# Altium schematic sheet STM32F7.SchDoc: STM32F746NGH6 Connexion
size A3; Date: 25-FEB-2015; Author: A.B; CompanyName: STMicroelectronics; Address1: 12, Rue Jules HOROWITZ; Address2: 38019 Grenoble; Address3: FRANCE; DocumentNumber: MB1191; Revision: B-02; SheetNumber: 9; SheetTotal: 13; Project: STM32F746G-DISCO
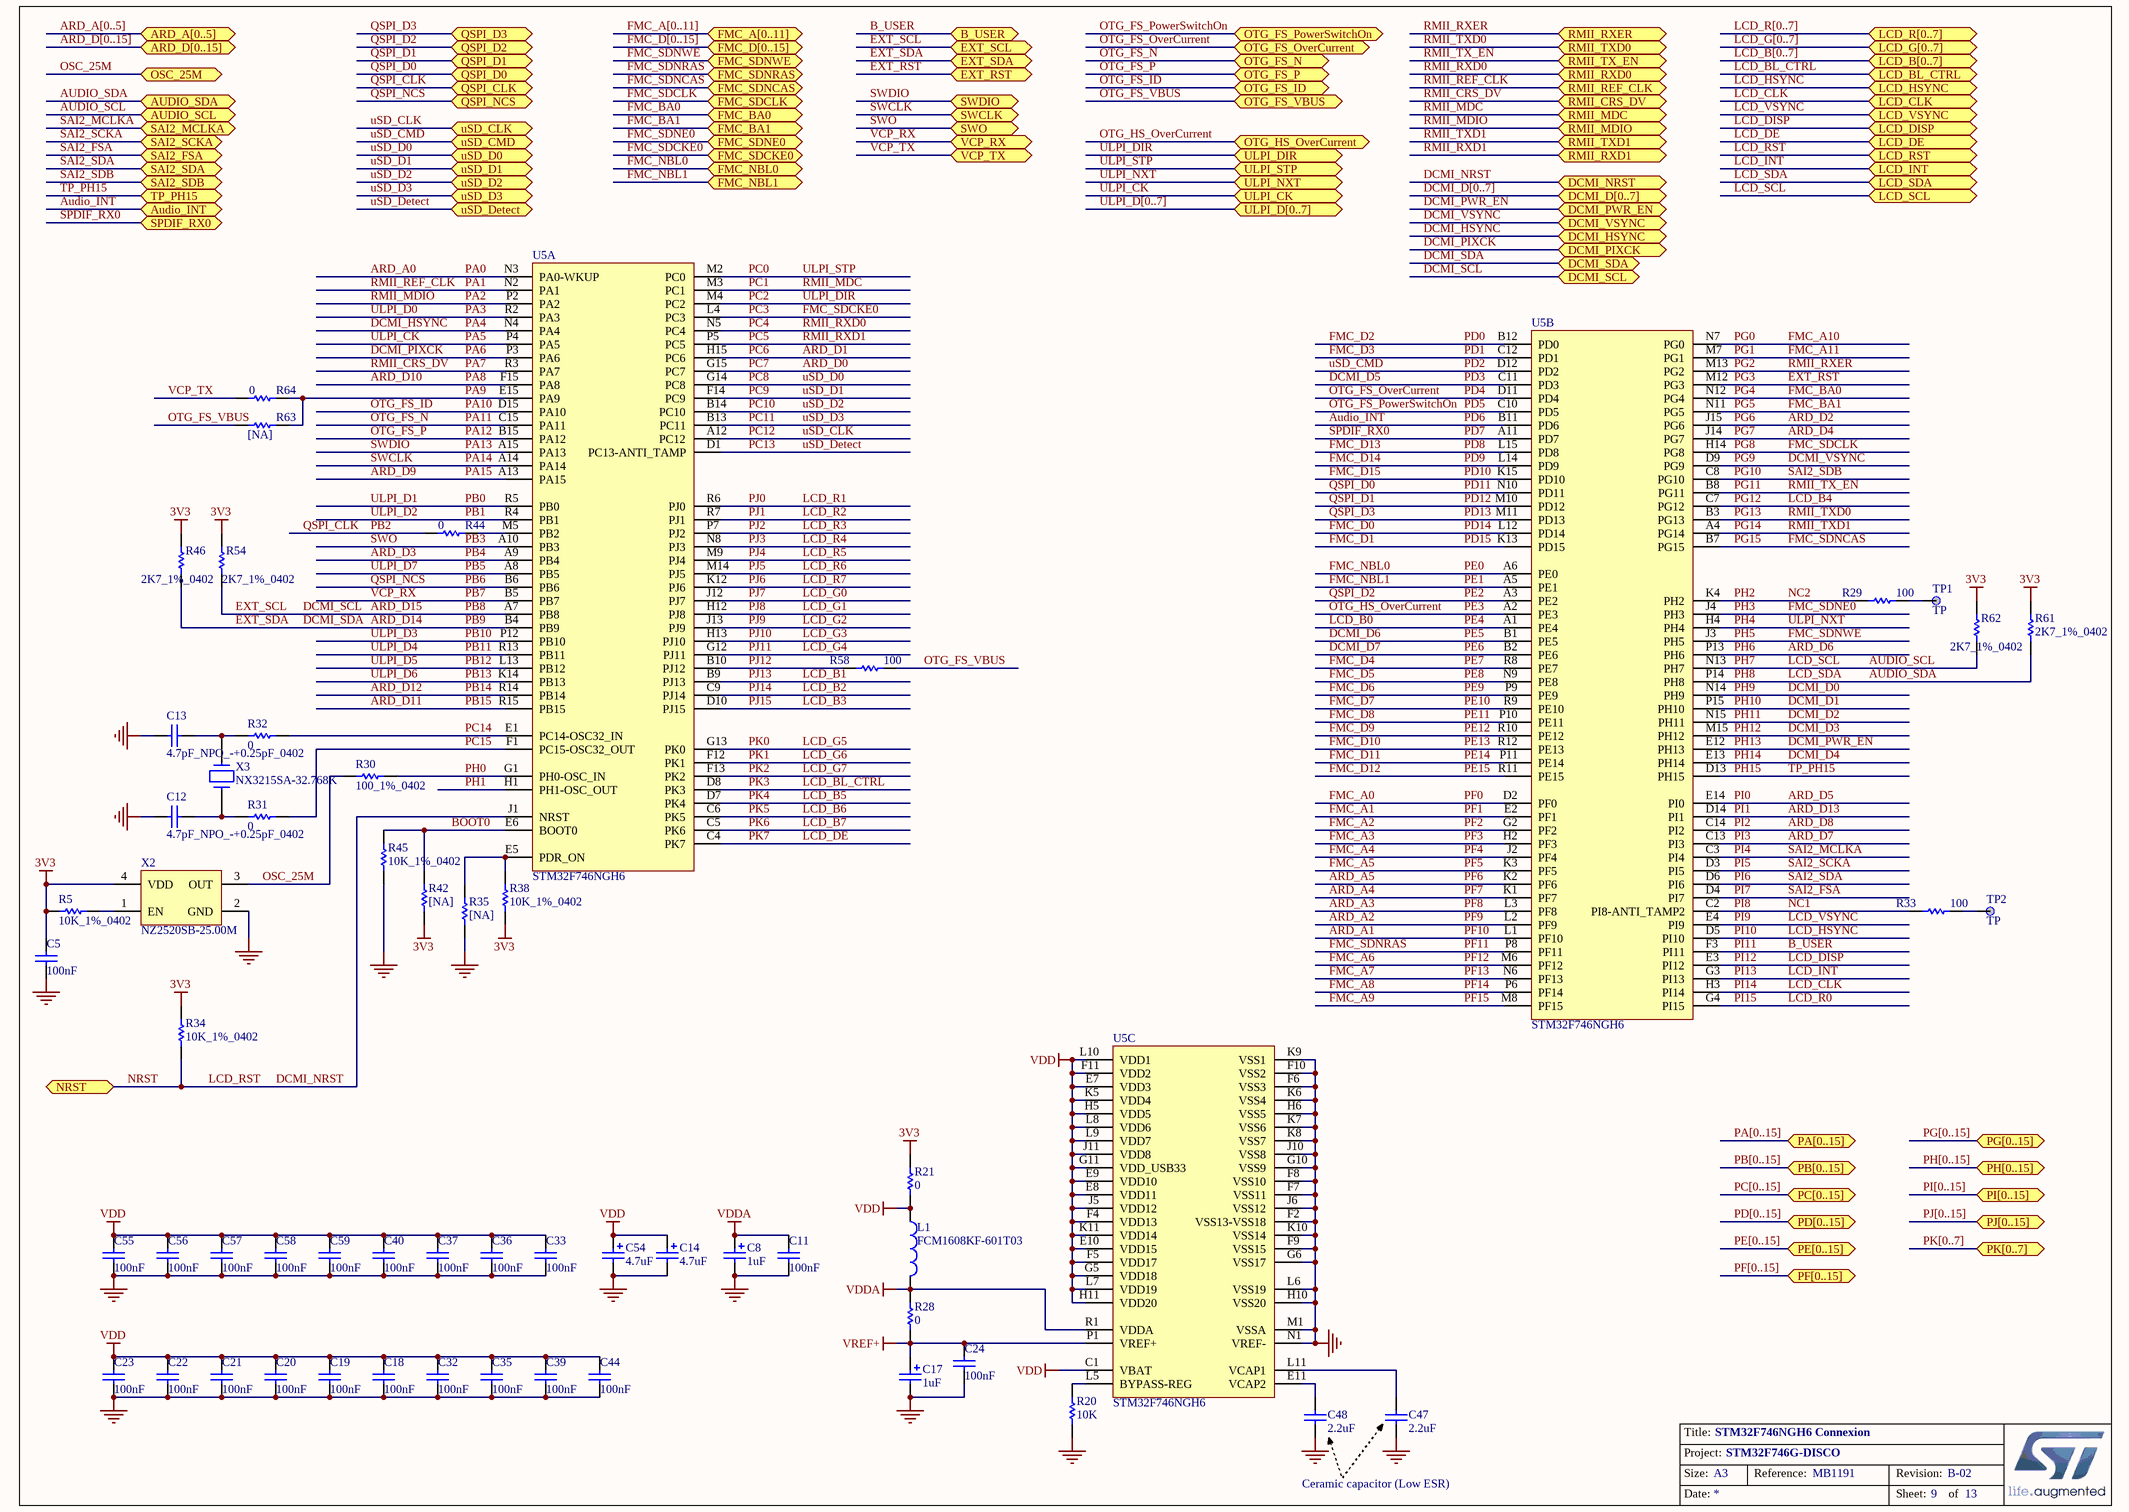
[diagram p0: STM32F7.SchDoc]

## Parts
C5  100nF  [0402C]
C8  1uF  [TAN-A]
C11  100nF  [0402C]
C12  4.7pF_NPO_-+0.25pF_0402  [0402C]
C13  4.7pF_NPO_-+0.25pF_0402  [0402C]
C14  4.7uF  [TAN-A]
C17  1uF  [TAN-A]
C18  100nF  [0402C]
C19  100nF  [0402C]
C20  100nF  [0402C]
C21  100nF  [0402C]
C22  100nF  [0402C]
C23  100nF  [0402C]
C24  100nF  [0402C]
C32  100nF  [0402C]
C33  100nF  [0402C]
C35  100nF  [0402C]
C36  100nF  [0402C]
C37  100nF  [0402C]
C39  100nF  [0402C]
C40  100nF  [0402C]
C44  100nF  [0402C]
C47  2.2uF  [1206C]
C48  2.2uF  [1206C]
C54  4.7uF  [TAN-A]
C55  100nF  [0402C]
C56  100nF  [0402C]
C57  100nF  [0402C]
C58  100nF  [0402C]
C59  100nF  [0402C]
L1  FCM1608KF-601T03  [0603L]
R5  10K_1%_0402  [0402R]
R20  10K  [0402R]
R21  0  [0603R-GS]
R28  0  [0603R-GS]
R29  100  [0402R]
R30  100_1%_0402  [0402R]
R31  0  [0402R]
R32  0  [0402R]
R33  100  [0402R]
R34  10K_1%_0402  [0402R]
R35  [NA]  [0402R]
R38  10K_1%_0402  [0402R]
R42  [NA]  [0402R]
R44  0  [0402R]
R45  10K_1%_0402  [0402R]
R46  2K7_1%_0402  [0402R]
R54  2K7_1%_0402  [0402R]
R58  100  [0402R]
R61  2K7_1%_0402  [0402R]
R62  2K7_1%_0402  [0402R]
R63  [NA]  [0402R]
R64  0  [0402R]
TP1  TP  [SMDTEST-1MM]
TP2  TP  [SMDTEST-1MM]
U5  STM32F746NGH6  [BGA216_0R8_13X13_SKT]  (parts A,B,C of 3)
X2  NZ2520SB-25.00M  [OSC_4SM_2R5X2R0]
X3  NX3215SA-32.768K  [XTAL_2SM_3R2X1R5]

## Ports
ARD_A[0..5], ARD_D[0..15], Audio_INT, AUDIO_SCL, AUDIO_SDA, B_USER, DCMI_D[0..7], DCMI_HSYNC, DCMI_NRST, DCMI_PIXCK, DCMI_PWR_EN, DCMI_SCL, DCMI_SDA, DCMI_VSYNC, EXT_RST, EXT_SCL, EXT_SDA, FMC_A[0..11], FMC_BA0, FMC_BA1, FMC_D[0..15], FMC_NBL0, FMC_NBL1, FMC_SDCKE0, FMC_SDCLK, FMC_SDNCAS, FMC_SDNE0, FMC_SDNRAS, FMC_SDNWE, LCD_B[0..7], LCD_BL_CTRL, LCD_CLK, LCD_DE, LCD_DISP, LCD_G[0..7], LCD_HSYNC, LCD_INT, LCD_R[0..7], LCD_RST, LCD_SCL, LCD_SDA, LCD_VSYNC, NRST, OSC_25M, OTG_FS_ID, OTG_FS_N, OTG_FS_OverCurrent, OTG_FS_P, OTG_FS_PowerSwitchOn, OTG_FS_VBUS, OTG_HS_OverCurrent, PA[0..15], PB[0..15], PC[0..15], PD[0..15], PE[0..15], PF[0..15], PG[0..15], PH[0..15], PI[0..15], PJ[0..15], PK[0..7], QSPI_CLK, QSPI_D0, QSPI_D1, QSPI_D2, QSPI_D3, QSPI_NCS, RMII_CRS_DV, RMII_MDC, RMII_MDIO, RMII_REF_CLK, RMII_RXD0, RMII_RXD1, RMII_RXER, RMII_TX_EN, RMII_TXD0, RMII_TXD1, SAI2_FSA, SAI2_MCLKA, SAI2_SCKA, SAI2_SDA, SAI2_SDB, SPDIF_RX0, SWCLK, SWDIO, SWO, TP_PH15, ULPI_CK, ULPI_D[0..7], ULPI_DIR, ULPI_NXT, ULPI_STP, uSD_CLK, uSD_CMD, uSD_D0, uSD_D1, uSD_D2, uSD_D3, uSD_Detect, VCP_RX, VCP_TX

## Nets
3V3: C5.2 R5.1 R21.2 R34.2 R38.1 R42.1 R46.2 R54.2 R61.2 R62.2 X2.4(VDD)
GND: C5.1 C8.2 C11.1 C12.1 C13.1 C14.2 C17.2 C18.1 C19.1 C20.1 C21.1 C22.1 C23.1 C24.1 C32.1 C33.1 C35.1 C36.1 C37.1 C39.1 C40.1 C44.1 C47.1 C48.1 C54.2 C55.1 C56.1 C57.1 C58.1 C59.1 R20.1 R35.1 R45.1 U5.F2(VSS13-VSS18) U5.F6(VSS3) U5.F7(VSS11) U5.F8(VSS10) U5.F9(VSS15) U5.F10(VSS2) U5.G6(VSS17) U5.G10(VSS9) U5.H6(VSS5) U5.H10(VSS20) U5.J6(VSS12) U5.J10(VSS8) U5.K6(VSS4) U5.K7(VSS6) U5.K8(VSS7) U5.K9(VSS1) U5.K10(VSS14) U5.L6(VSS19) U5.M1(VSSA) U5.N1(VREF-) X2.2(GND)
VDD: C14.1 C18.2 C19.2 C20.2 C21.2 C22.2 C23.2 C32.2 C33.2 C35.2 C36.2 C37.2 C39.2 C40.2 C44.2 C54.1 C55.2 C56.2 C57.2 C58.2 C59.2 L1.1 R21.1 U5.C1(VBAT) U5.E7(VDD3) U5.E8(VDD11) U5.E9(VDD10) U5.E10(VDD15) U5.F4(VDD13) U5.F5(VDD17) U5.F11(VDD2) U5.G5(VDD18) U5.G11(VDD_USB33) U5.H5(VDD5) U5.H11(VDD20) U5.J5(VDD12) U5.J11(VDD8) U5.K5(VDD4) U5.K11(VDD14) U5.L7(VDD19) U5.L8(VDD6) U5.L9(VDD7) U5.L10(VDD1)
VDDA: C8.1 C11.2 L1.2 R28.1 U5.R1(VDDA)
VREF+: C17.1 C24.2 R28.2 U5.P1(VREF+)
ARD_A0: U5.N3(PA0-WKUP)  [also labelled PA0]
ARD_A1: U5.L1(PF10)  [also labelled PF10]
ARD_A2: U5.L2(PF9)  [also labelled PF9]
ARD_A3: U5.L3(PF8)  [also labelled PF8]
ARD_A4: U5.K1(PF7)  [also labelled PF7]
ARD_A5: U5.K2(PF6)  [also labelled PF6]
ARD_D0: U5.G15(PC7)  [also labelled PC7]
ARD_D1: U5.H15(PC6)  [also labelled PC6]
ARD_D2: U5.J15(PG6)  [also labelled PG6]
ARD_D3: U5.A9(PB4)  [also labelled PB4]
ARD_D4: U5.J14(PG7)  [also labelled PG7]
ARD_D5: U5.E14(PI0)  [also labelled PI0]
ARD_D6: U5.P13(PH6)  [also labelled PH6]
ARD_D7: U5.C13(PI3)  [also labelled PI3]
ARD_D8: U5.C14(PI2)  [also labelled PI2]
ARD_D9: U5.A13(PA15)  [also labelled PA15]
ARD_D10: U5.F15(PA8)  [also labelled PA8]
ARD_D11: U5.R15(PB15)  [also labelled PB15]
ARD_D12: U5.R14(PB14)  [also labelled PB14]
ARD_D13: U5.D14(PI1)  [also labelled PI1]
ARD_D14: R46.1 U5.B4(PB9) ; port DCMI_SDA, port EXT_SDA  [also labelled DCMI_SDA, EXT_SDA, PB9]
ARD_D15: R54.1 U5.A7(PB8) ; port DCMI_SCL, port EXT_SCL  [also labelled DCMI_SCL, EXT_SCL, PB8]
Audio_INT: U5.B11(PD6) ; port Audio_INT  [also labelled PD6]
AUDIO_SCL: R62.1 U5.N13(PH7) ; port LCD_SCL, port AUDIO_SCL  [also labelled LCD_SCL, PH7]
AUDIO_SDA: R61.1 U5.P14(PH8) ; port LCD_SDA, port AUDIO_SDA  [also labelled LCD_SDA, PH8]
B_USER: U5.F3(PI11) ; port B_USER  [also labelled PI11]
BOOT0: R42.2 R45.2 U5.E6(BOOT0)
DCMI_D0: U5.N14(PH9)  [also labelled PH9]
DCMI_D1: U5.P15(PH10)  [also labelled PH10]
DCMI_D2: U5.N15(PH11)  [also labelled PH11]
DCMI_D3: U5.M15(PH12)  [also labelled PH12]
DCMI_D4: U5.E13(PH14)  [also labelled PH14]
DCMI_D5: U5.C11(PD3)  [also labelled PD3]
DCMI_D6: U5.B1(PE5)  [also labelled PE5]
DCMI_D7: U5.B2(PE6)  [also labelled PE6]
DCMI_HSYNC: U5.N4(PA4) ; port DCMI_HSYNC  [also labelled PA4]
DCMI_NRST: R34.1 U5.J1(NRST) ; port NRST, port LCD_RST, port DCMI_NRST  [also labelled LCD_RST, NRST]
DCMI_PIXCK: U5.P3(PA6) ; port DCMI_PIXCK  [also labelled PA6]
DCMI_PWR_EN: U5.E12(PH13) ; port DCMI_PWR_EN  [also labelled PH13]
DCMI_VSYNC: U5.D9(PG9) ; port DCMI_VSYNC  [also labelled PG9]
EXT_RST: U5.M12(PG3) ; port EXT_RST  [also labelled PG3]
FMC_A0: U5.D2(PF0)  [also labelled PF0]
FMC_A1: U5.E2(PF1)  [also labelled PF1]
FMC_A2: U5.G2(PF2)  [also labelled PF2]
FMC_A3: U5.H2(PF3)  [also labelled PF3]
FMC_A4: U5.J2(PF4)  [also labelled PF4]
FMC_A5: U5.K3(PF5)  [also labelled PF5]
FMC_A6: U5.M6(PF12)  [also labelled PF12]
FMC_A7: U5.N6(PF13)  [also labelled PF13]
FMC_A8: U5.P6(PF14)  [also labelled PF14]
FMC_A9: U5.M8(PF15)  [also labelled PF15]
FMC_A10: U5.N7(PG0)  [also labelled PG0]
FMC_A11: U5.M7(PG1)  [also labelled PG1]
FMC_BA0: U5.N12(PG4) ; port FMC_BA0  [also labelled PG4]
FMC_BA1: U5.N11(PG5) ; port FMC_BA1  [also labelled PG5]
FMC_D0: U5.L12(PD14)  [also labelled PD14]
FMC_D1: U5.K13(PD15)  [also labelled PD15]
FMC_D2: U5.B12(PD0)  [also labelled PD0]
FMC_D3: U5.C12(PD1)  [also labelled PD1]
FMC_D4: U5.R8(PE7)  [also labelled PE7]
FMC_D5: U5.N9(PE8)  [also labelled PE8]
FMC_D6: U5.P9(PE9)  [also labelled PE9]
FMC_D7: U5.R9(PE10)  [also labelled PE10]
FMC_D8: U5.P10(PE11)  [also labelled PE11]
FMC_D9: U5.R10(PE12)  [also labelled PE12]
FMC_D10: U5.R12(PE13)  [also labelled PE13]
FMC_D11: U5.P11(PE14)  [also labelled PE14]
FMC_D12: U5.R11(PE15)  [also labelled PE15]
FMC_D13: U5.L15(PD8)  [also labelled PD8]
FMC_D14: U5.L14(PD9)  [also labelled PD9]
FMC_D15: U5.K15(PD10)  [also labelled PD10]
FMC_NBL0: U5.A6(PE0) ; port FMC_NBL0  [also labelled PE0]
FMC_NBL1: U5.A5(PE1) ; port FMC_NBL1  [also labelled PE1]
FMC_SDCKE0: U5.L4(PC3) ; port FMC_SDCKE0  [also labelled PC3]
FMC_SDCLK: U5.H14(PG8) ; port FMC_SDCLK  [also labelled PG8]
FMC_SDNCAS: U5.B7(PG15) ; port FMC_SDNCAS  [also labelled PG15]
FMC_SDNE0: U5.J4(PH3) ; port FMC_SDNE0  [also labelled PH3]
FMC_SDNRAS: U5.P8(PF11) ; port FMC_SDNRAS  [also labelled PF11]
FMC_SDNWE: U5.J3(PH5) ; port FMC_SDNWE  [also labelled PH5]
LCD_B0: U5.A1(PE4)  [also labelled PE4]
LCD_B1: U5.B9(PJ13)  [also labelled PJ13]
LCD_B2: U5.C9(PJ14)  [also labelled PJ14]
LCD_B3: U5.D10(PJ15)  [also labelled PJ15]
LCD_B4: U5.C7(PG12)  [also labelled PG12]
LCD_B5: U5.D7(PK4)  [also labelled PK4]
LCD_B6: U5.C6(PK5)  [also labelled PK5]
LCD_B7: U5.C5(PK6)  [also labelled PK6]
LCD_BL_CTRL: U5.D8(PK3) ; port LCD_BL_CTRL  [also labelled PK3]
LCD_CLK: U5.H3(PI14) ; port LCD_CLK  [also labelled PI14]
LCD_DE: U5.C4(PK7) ; port LCD_DE  [also labelled PK7]
LCD_DISP: U5.E3(PI12) ; port LCD_DISP  [also labelled PI12]
LCD_G0: U5.J12(PJ7)  [also labelled PJ7]
LCD_G1: U5.H12(PJ8)  [also labelled PJ8]
LCD_G2: U5.J13(PJ9)  [also labelled PJ9]
LCD_G3: U5.H13(PJ10)  [also labelled PJ10]
LCD_G4: U5.G12(PJ11)  [also labelled PJ11]
LCD_G5: U5.G13(PK0)  [also labelled PK0]
LCD_G6: U5.F12(PK1)  [also labelled PK1]
LCD_G7: U5.F13(PK2)  [also labelled PK2]
LCD_HSYNC: U5.D5(PI10) ; port LCD_HSYNC  [also labelled PI10]
LCD_INT: U5.G3(PI13) ; port LCD_INT  [also labelled PI13]
LCD_R0: U5.G4(PI15)  [also labelled PI15]
LCD_R1: U5.R6(PJ0)  [also labelled PJ0]
LCD_R2: U5.R7(PJ1)  [also labelled PJ1]
LCD_R3: U5.P7(PJ2)  [also labelled PJ2]
LCD_R4: U5.N8(PJ3)  [also labelled PJ3]
LCD_R5: U5.M9(PJ4)  [also labelled PJ4]
LCD_R6: U5.M14(PJ5)  [also labelled PJ5]
LCD_R7: U5.K12(PJ6)  [also labelled PJ6]
LCD_VSYNC: U5.E4(PI9) ; port LCD_VSYNC  [also labelled PI9]
NC1: R33.1 U5.C2(PI8-ANTI_TAMP2)  [also labelled PI8]
NC2: R29.1 U5.K4(PH2)  [also labelled PH2]
OSC_25M: R30.1 X2.3(OUT) ; port OSC_25M
OTG_FS_ID: U5.D15(PA10) ; port OTG_FS_ID  [also labelled PA10]
OTG_FS_N: U5.C15(PA11) ; port OTG_FS_N  [also labelled PA11]
OTG_FS_OverCurrent: U5.D11(PD4) ; port OTG_FS_OverCurrent  [also labelled PD4]
OTG_FS_P: U5.B15(PA12) ; port OTG_FS_P  [also labelled PA12]
OTG_FS_PowerSwitchOn: U5.C10(PD5) ; port OTG_FS_PowerSwitchOn  [also labelled PD5]
OTG_FS_VBUS: R58.2 R63.1 ; port OTG_FS_VBUS
OTG_HS_OverCurrent: U5.A2(PE3) ; port OTG_HS_OverCurrent  [also labelled PE3]
PA1: U5.N2(PA1) ; port RMII_REF_CLK  [also labelled RMII_REF_CLK]
PA2: U5.P2(PA2) ; port RMII_MDIO  [also labelled RMII_MDIO]
PA3: U5.R2(PA3)  [also labelled ULPI_D0]
PA5: U5.P4(PA5) ; port ULPI_CK  [also labelled ULPI_CK]
PA7: U5.R3(PA7) ; port RMII_CRS_DV  [also labelled RMII_CRS_DV]
PA9: R63.2 R64.2 U5.E15(PA9)
PA13: U5.A15(PA13) ; port SWDIO  [also labelled SWDIO]
PA14: U5.A14(PA14) ; port SWCLK  [also labelled SWCLK]
PB0: U5.R5(PB0)  [also labelled ULPI_D1]
PB1: U5.R4(PB1)  [also labelled ULPI_D2]
PB2: R44.1 ; port QSPI_CLK  [also labelled QSPI_CLK]
PB3: U5.A10(PB3) ; port SWO  [also labelled SWO]
PB5: U5.A8(PB5)  [also labelled ULPI_D7]
PB6: U5.B6(PB6) ; port QSPI_NCS  [also labelled QSPI_NCS]
PB7: U5.B5(PB7) ; port VCP_RX  [also labelled VCP_RX]
PB10: U5.P12(PB10)  [also labelled ULPI_D3]
PB11: U5.R13(PB11)  [also labelled ULPI_D4]
PB12: U5.L13(PB12)  [also labelled ULPI_D5]
PB13: U5.K14(PB13)  [also labelled ULPI_D6]
PC0: U5.M2(PC0) ; port ULPI_STP  [also labelled ULPI_STP]
PC1: U5.M3(PC1) ; port RMII_MDC  [also labelled RMII_MDC]
PC2: U5.M4(PC2) ; port ULPI_DIR  [also labelled ULPI_DIR]
PC4: U5.N5(PC4) ; port RMII_RXD0  [also labelled RMII_RXD0]
PC5: U5.P5(PC5) ; port RMII_RXD1  [also labelled RMII_RXD1]
PC8: U5.G14(PC8) ; port uSD_D0  [also labelled uSD_D0]
PC9: U5.F14(PC9) ; port uSD_D1  [also labelled uSD_D1]
PC10: U5.B14(PC10) ; port uSD_D2  [also labelled uSD_D2]
PC11: U5.B13(PC11) ; port uSD_D3  [also labelled uSD_D3]
PC12: U5.A12(PC12) ; port uSD_CLK  [also labelled uSD_CLK]
PC13: U5.D1(PC13-ANTI_TAMP) ; port uSD_Detect  [also labelled uSD_Detect]
PC14: R32.2 U5.E1(PC14-OSC32_IN)
PC15: R31.2 U5.F1(PC15-OSC32_OUT)
PD2: U5.D12(PD2) ; port uSD_CMD  [also labelled uSD_CMD]
PD7: U5.A11(PD7) ; port SPDIF_RX0  [also labelled SPDIF_RX0]
PD11: U5.N10(PD11) ; port QSPI_D0  [also labelled QSPI_D0]
PD12: U5.M10(PD12) ; port QSPI_D1  [also labelled QSPI_D1]
PD13: U5.M11(PD13) ; port QSPI_D3  [also labelled QSPI_D3]
PE2: U5.A3(PE2) ; port QSPI_D2  [also labelled QSPI_D2]
PG2: U5.M13(PG2) ; port RMII_RXER  [also labelled RMII_RXER]
PG10: U5.C8(PG10) ; port SAI2_SDB  [also labelled SAI2_SDB]
PG11: U5.B8(PG11) ; port RMII_TX_EN  [also labelled RMII_TX_EN]
PG13: U5.B3(PG13) ; port RMII_TXD0  [also labelled RMII_TXD0]
PG14: U5.A4(PG14) ; port RMII_TXD1  [also labelled RMII_TXD1]
PH0: R30.2 U5.G1(PH0-OSC_IN)
PH1: U5.H1(PH1-OSC_OUT)
PH4: U5.H4(PH4) ; port ULPI_NXT  [also labelled ULPI_NXT]
PH15: U5.D13(PH15) ; port TP_PH15  [also labelled TP_PH15]
PI4: U5.C3(PI4) ; port SAI2_MCLKA  [also labelled SAI2_MCLKA]
PI5: U5.D3(PI5) ; port SAI2_SCKA  [also labelled SAI2_SCKA]
PI6: U5.D6(PI6) ; port SAI2_SDA  [also labelled SAI2_SDA]
PI7: U5.D4(PI7) ; port SAI2_FSA  [also labelled SAI2_FSA]
PJ12: R58.1 U5.B10(PJ12)
VCP_TX: R64.1 ; port VCP_TX
NetC12_2: C12.2 R31.1 X3.2
NetC13_2: C13.2 R32.1 X3.1
NetC47_2: C47.2 U5.L11(VCAP1)
NetC48_2: C48.2 U5.E11(VCAP2)
NetR5_2: R5.2 X2.1(EN)
NetR20_2: R20.2 U5.L5(BYPASS-REG)
NetR29_2: R29.2 TP1.1
NetR33_2: R33.2 TP2.1
NetR35_2: R35.2 R38.2 U5.E5(PDR_ON)
NetR44_2: R44.2 U5.M5(PB2)

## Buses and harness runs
bus ARD_A[0..5] = port ARD_A[0..5]
bus ARD_D[0..15] = port ARD_D[0..15]
bus DCMI_D[0..7] = port DCMI_D[0..7]
bus FMC_A[0..11] = port FMC_A[0..11]
bus FMC_D[0..15] = port FMC_D[0..15]
bus LCD_B[0..7] = port LCD_B[0..7]
bus LCD_G[0..7] = port LCD_G[0..7]
bus LCD_R[0..7] = port LCD_R[0..7]
bus PA[0..15] = port PA[0..15]
bus PB[0..15] = port PB[0..15]
bus PC[0..15] = port PC[0..15]
bus PD[0..15] = port PD[0..15]
bus PE[0..15] = port PE[0..15]
bus PF[0..15] = port PF[0..15]
bus PG[0..15] = port PG[0..15]
bus PH[0..15] = port PH[0..15]
bus PI[0..15] = port PI[0..15]
bus PJ[0..15] = port PJ[0..15]
bus PK[0..7] = port PK[0..7]
bus ULPI_D[0..7] = port ULPI_D[0..7]

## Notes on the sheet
- Ceramic capacitor (Low ESR)

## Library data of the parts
C5 C11 C18-C24 C32 C33 C35-C37 C39 C40 C44 C55-C59 = Cap_100nF_X7R_10%_0402: Capacitor,100nF,16V,X7R,10%,0402,YAGEO; Manuf_Part_1: CC0402KRX7R7BB104
C8 C17 = Cap_1uF_POL_10%_TANA: Polarized Capacitor,1uF,16V,10%,typeA,AVX; Manuf_Part_1: TAJA105K016R
C12 C13 = Cap_4.7pF_NPO_-+0.25pF_0402: Capacitor, 4.7pF, 50V, NPO, -+0.25pF, 0402, YAGEO; Manuf_Part_1: CC0402CRNPO9BN4R7; Order: 311-1367-2-ND
C14 C54 = Cap_4.7uF_POL_10%_TANA: Polarized Capacitor,4.7uF,16V,10%,typeA,AVX; Manuf_Part_1: TAJA475K016R
C47 C48 = Cap_2.2uF_X7R_10%_1206: Capacitor,2.2uF,16V, X7R,10%,1206,YAGEO; Manuf_Part_1: CC1206KKX7R7BB225; Manuf_Part_2: C1206C225K4RAC; Manuf_2: KEMET
L1 = BEAD_600R_350MA_0603: Bead,600R,350mA,0603,FCM1608KF-601T03,Tai-tech; Manuf_2: TDK; Manuf_Part_2: MPZ1608S300A; Manuf_Part_3: BLM18PG121SN1D; Manuf_3: MURATA; Value: 100uH; Description_2: Bead,30R,5A,0603,MPZ1608S300A,TDK; Description_3: Bead,120R,2A,0603,BLM18PG121SN1D,MURATA
R5 R20 R34 R38 R45 = Res_10K_1%_0402: Resistor,10K,0402,1%,YAGEO; Manuf_Part_1: RC0402FR-0710KL
R21 R28 = Res_0_5%_0603: Resistor,0,0603,5%,YAGEO; Manuf_Part_1: RC0603JR-070RL; Order: 2363481
R29 R33 R58 = Res_100_1%_0402: Resistor,100,0402,1%,YAGEO; Manuf_Part_1: RC0402FR-07100RL; Order: 9239111
R30 = Res_100_1%_0402: Resistor,100,0402,1%,YAGEO; Manuf_Part_1: RC0402FR-07100RL; Value: 100; Order: 9239111
R31 R32 R44 R64 = Res_0_5%_0402: Resistor,0,0402,5%,YAGEO; Manuf_Part_1: RC0402JR-070RL; Order: 2363467
R35 R42 R63 = Res_NA_0402: Resistor,[NA],0402; Fitted: NO
R46 R54 R61 R62 = Res_2K7_1%_0402: Resistor,2K7,0402,1%,YAGEO; Manuf_Part_1: RC0402FR-072K7L
TP1 TP2 = TP: Test Point; Description: Test Point CMS
U5 = STM32F746NGH6U: STM32F746NGH6 (STM32F7 Birdie) TBGA216; Manuf_1: STM; ECCN_US/EU: 3A991A2/NEC; Ref St: 9175176; Provided: ST
X2 = OSC_25M_NZ2520SB: Oscillator 25.00Mhz, -+50PPM, 3.3V, Temp -55 to +125°C; Manuf_Part_1: NZ2520SB 25MHz END4869B; Manuf_1: NDK; Manuf_Part_2: KC2520B25.0000C10E00; Manuf_2: AVX Corp/Kyocera Corp; ECCN_US/EU: EAR99/NEC; Ref St: 9157031; Provided: ST
X3 = XTAL_32K_NX3215SA: Crystal 32.768kHz, 6pF, -+20PPM, R=50K, SMD; Manuf_1: NDK; Manuf_Part_1: NX3215SA 32.768KHz EXS00A-MU00525; Description: Crystal 32.768kHz, 6pF, -+20PPM, NDK only for ST, Type NX3215SA,  NDK Spec EXS00A-MU00525; ECCN_US/EU: EAR99/NEC; Ref St: 9157034; NDK Ref: X3101802; Provided: ST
